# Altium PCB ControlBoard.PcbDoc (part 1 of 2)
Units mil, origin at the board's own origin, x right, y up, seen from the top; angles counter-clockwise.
Board outline 2798 x 1675 mil, 4 copper layers (Top Layer, Layer 1, Layer 2, Bottom Layer), stack 62.493 mil thick; 143 components, 84 nets, 457 pads, 255 vias.
Unrouted connection lines stored in the file: 49.
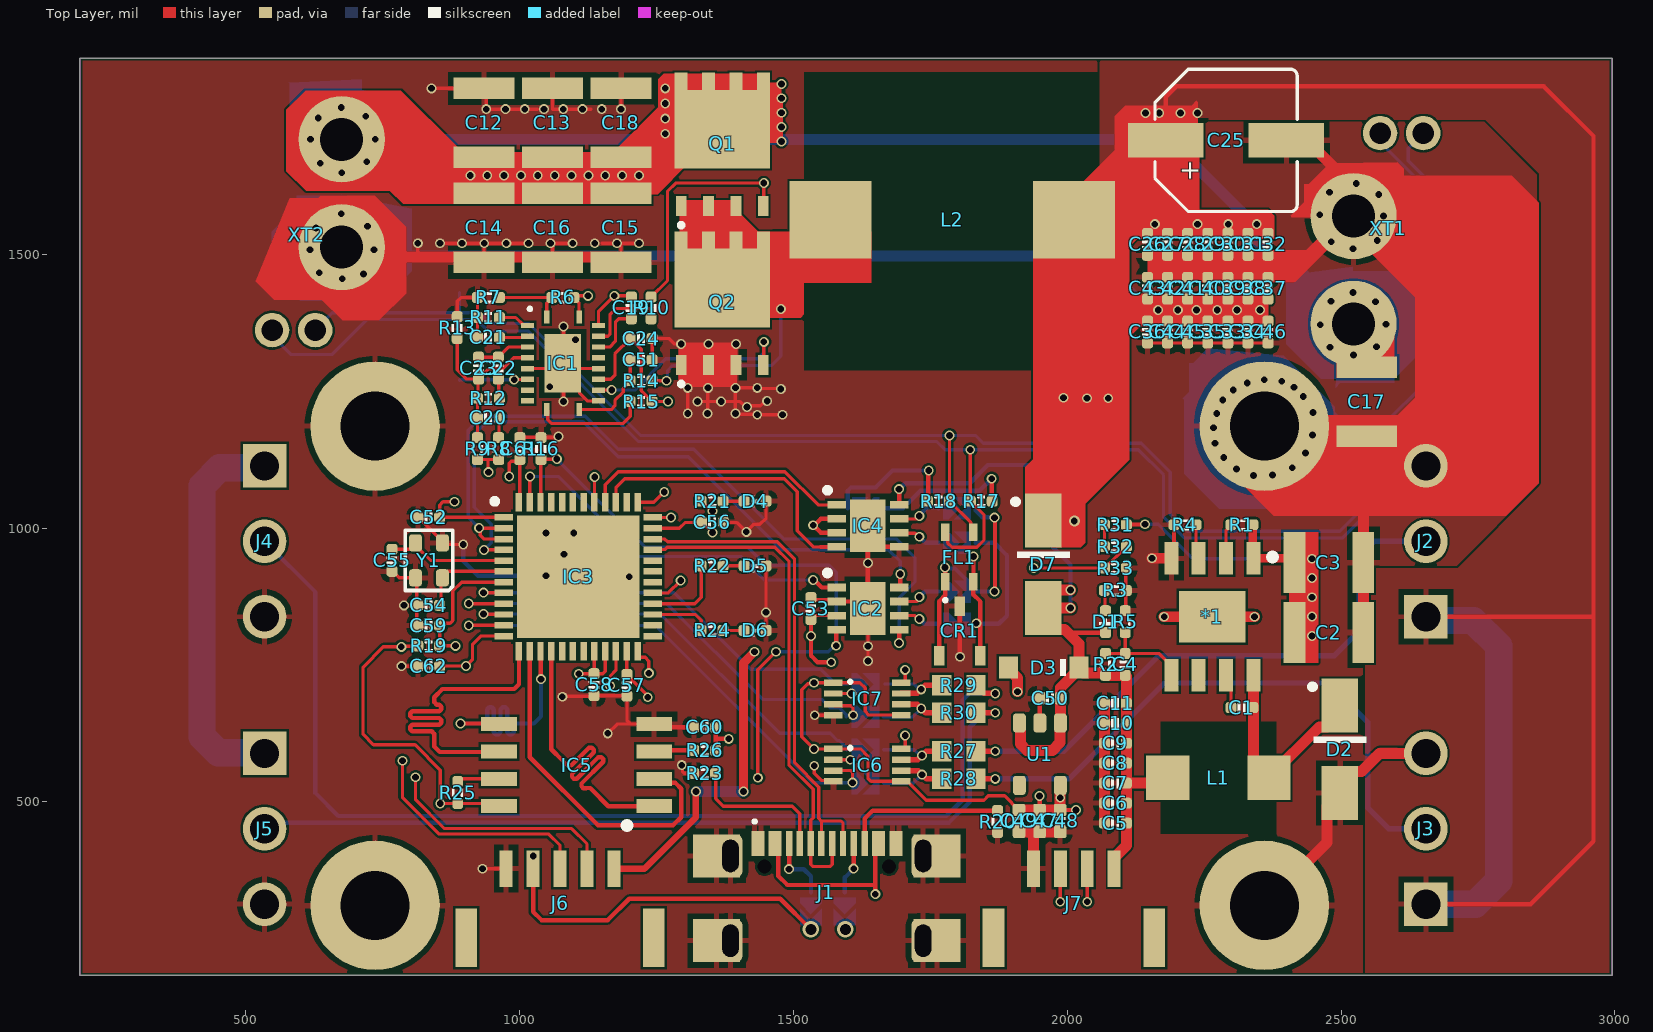
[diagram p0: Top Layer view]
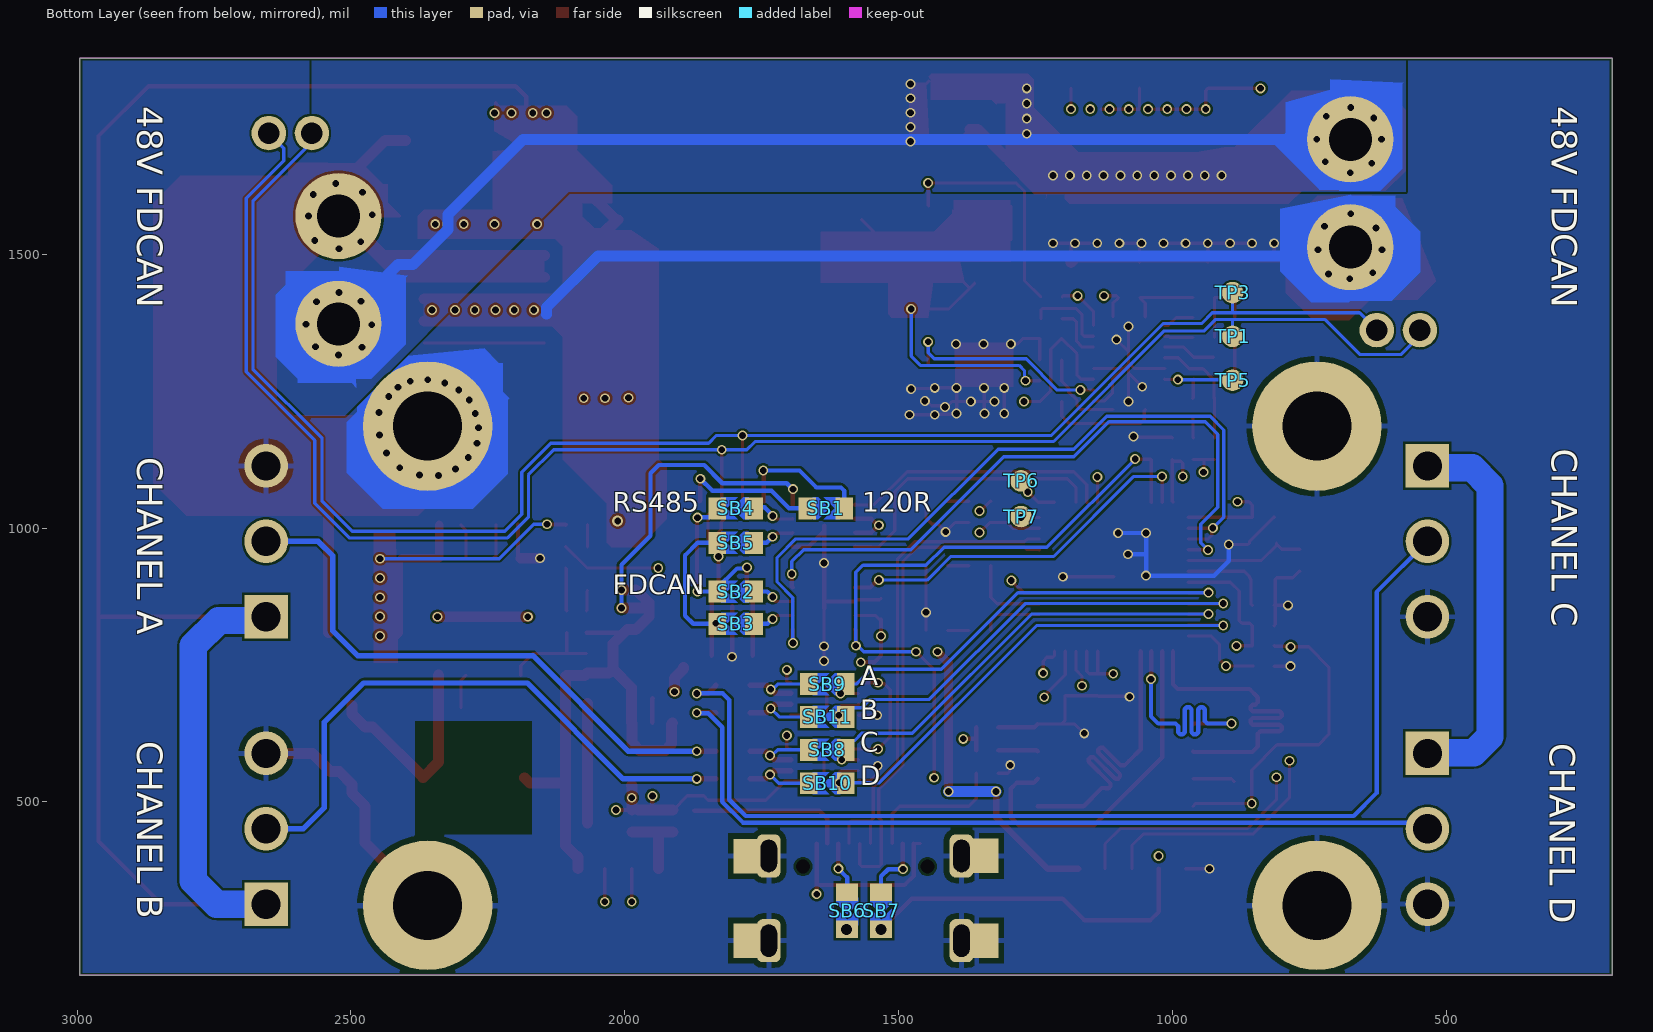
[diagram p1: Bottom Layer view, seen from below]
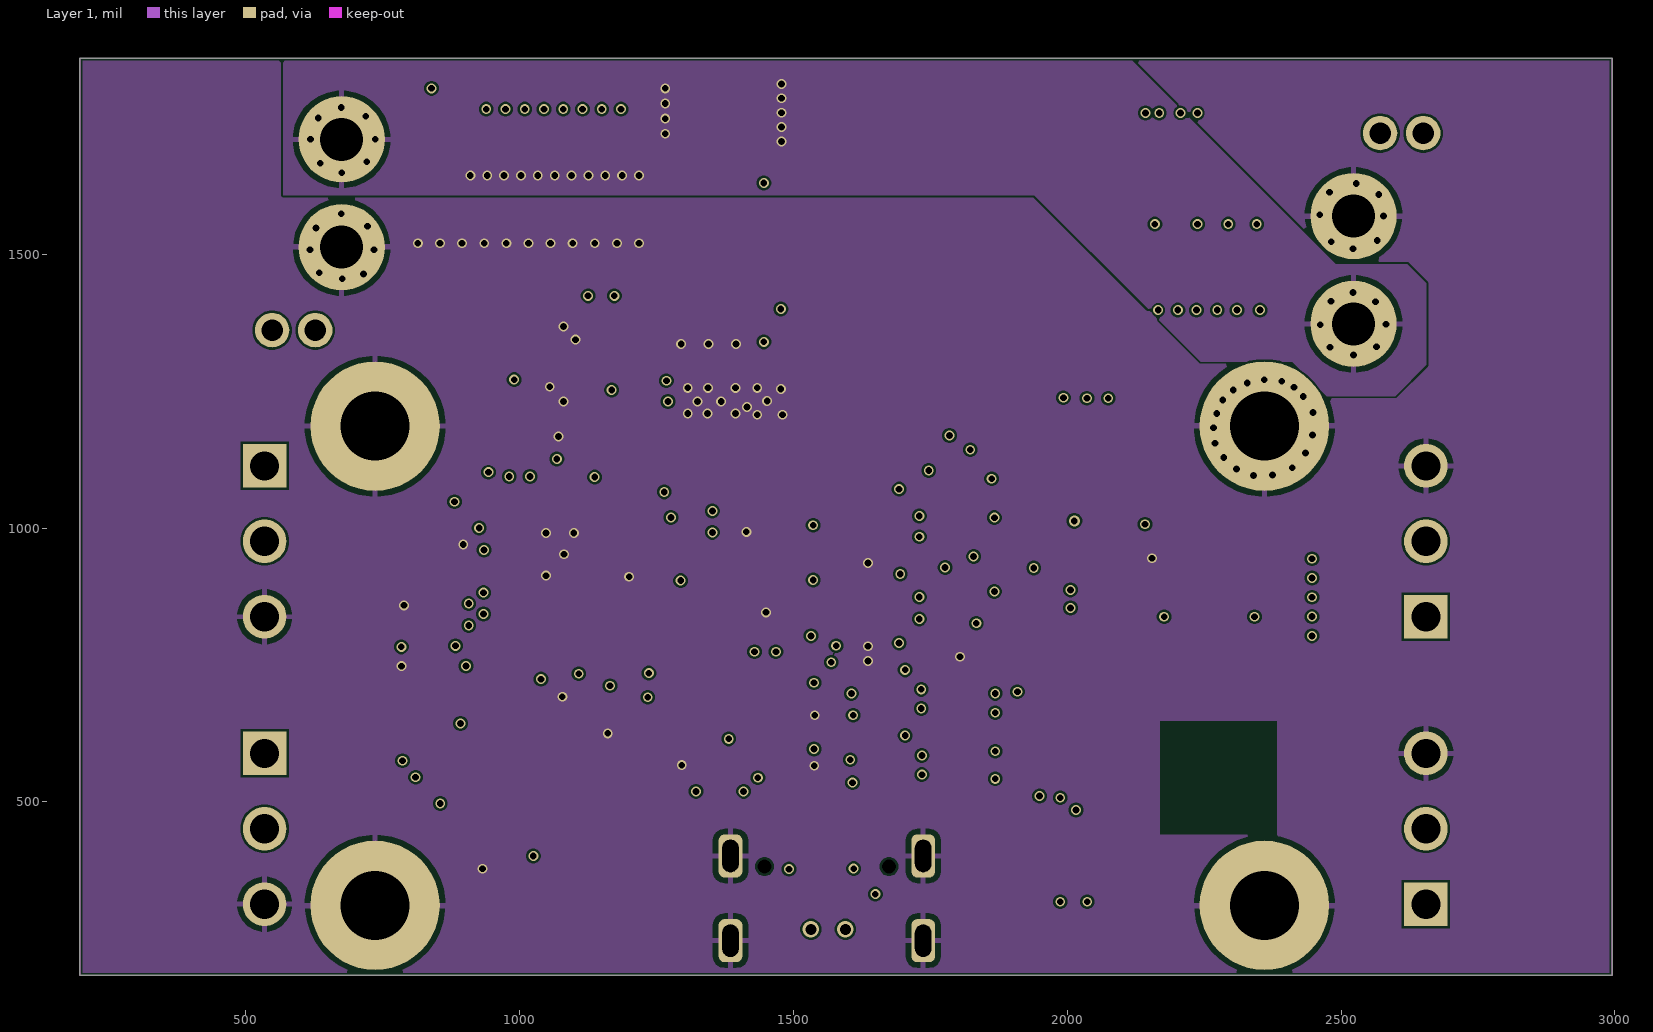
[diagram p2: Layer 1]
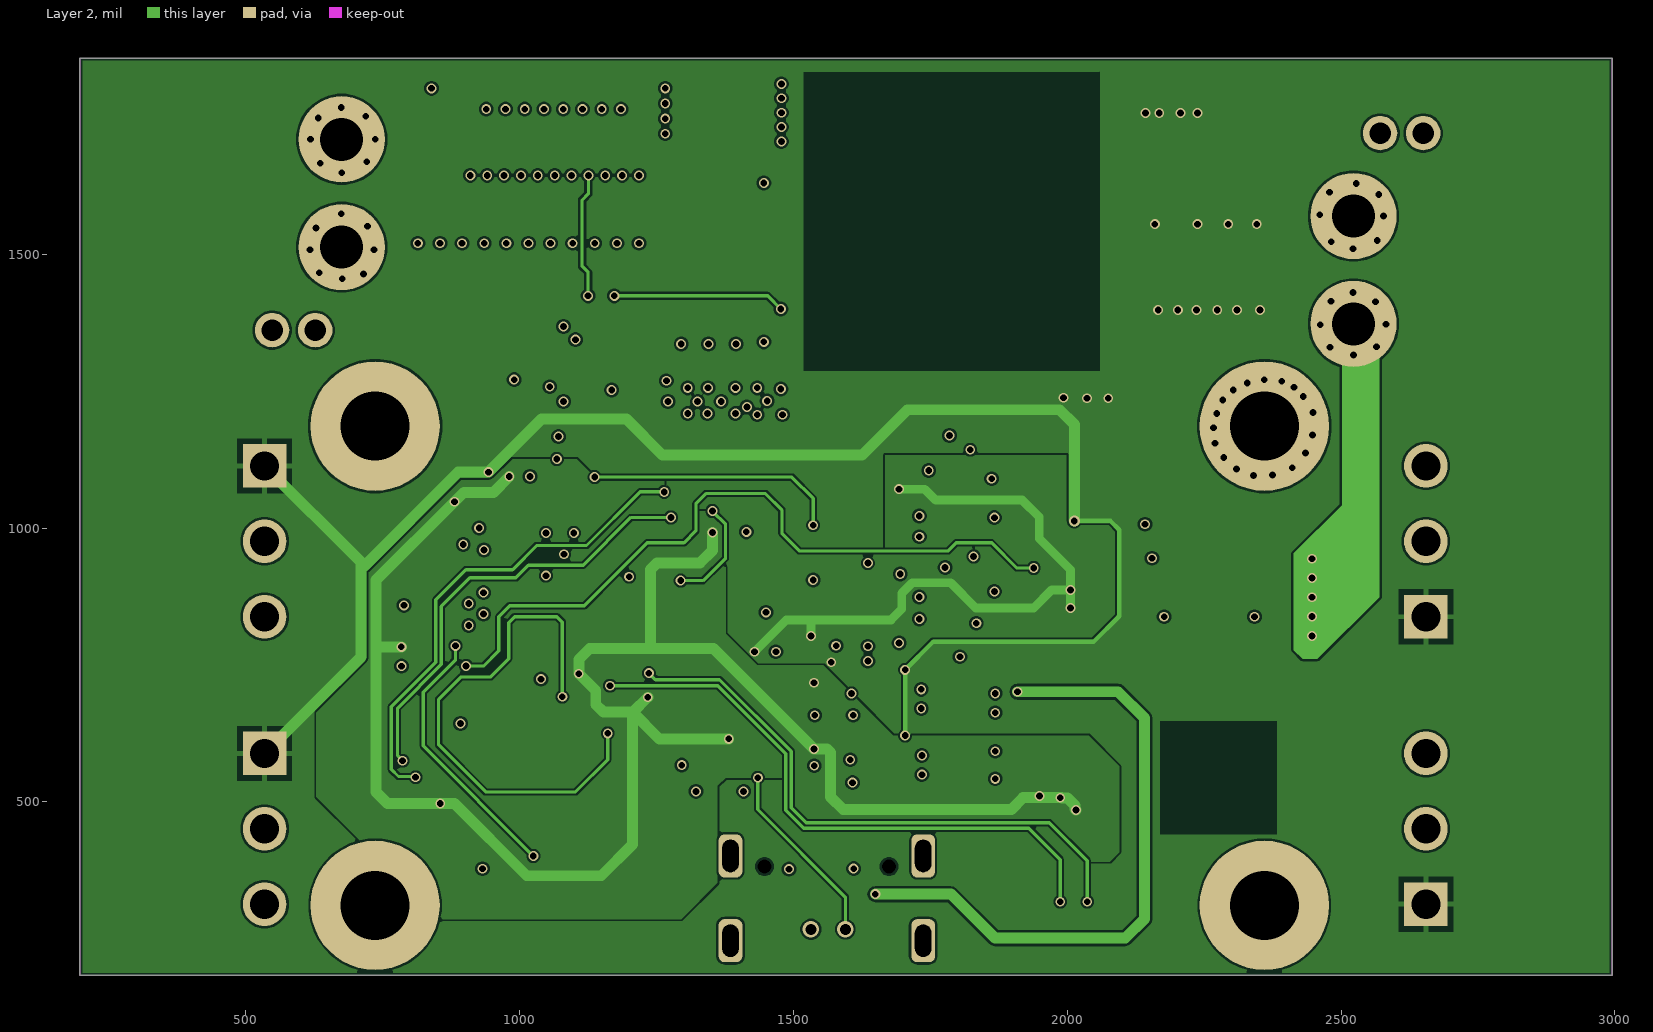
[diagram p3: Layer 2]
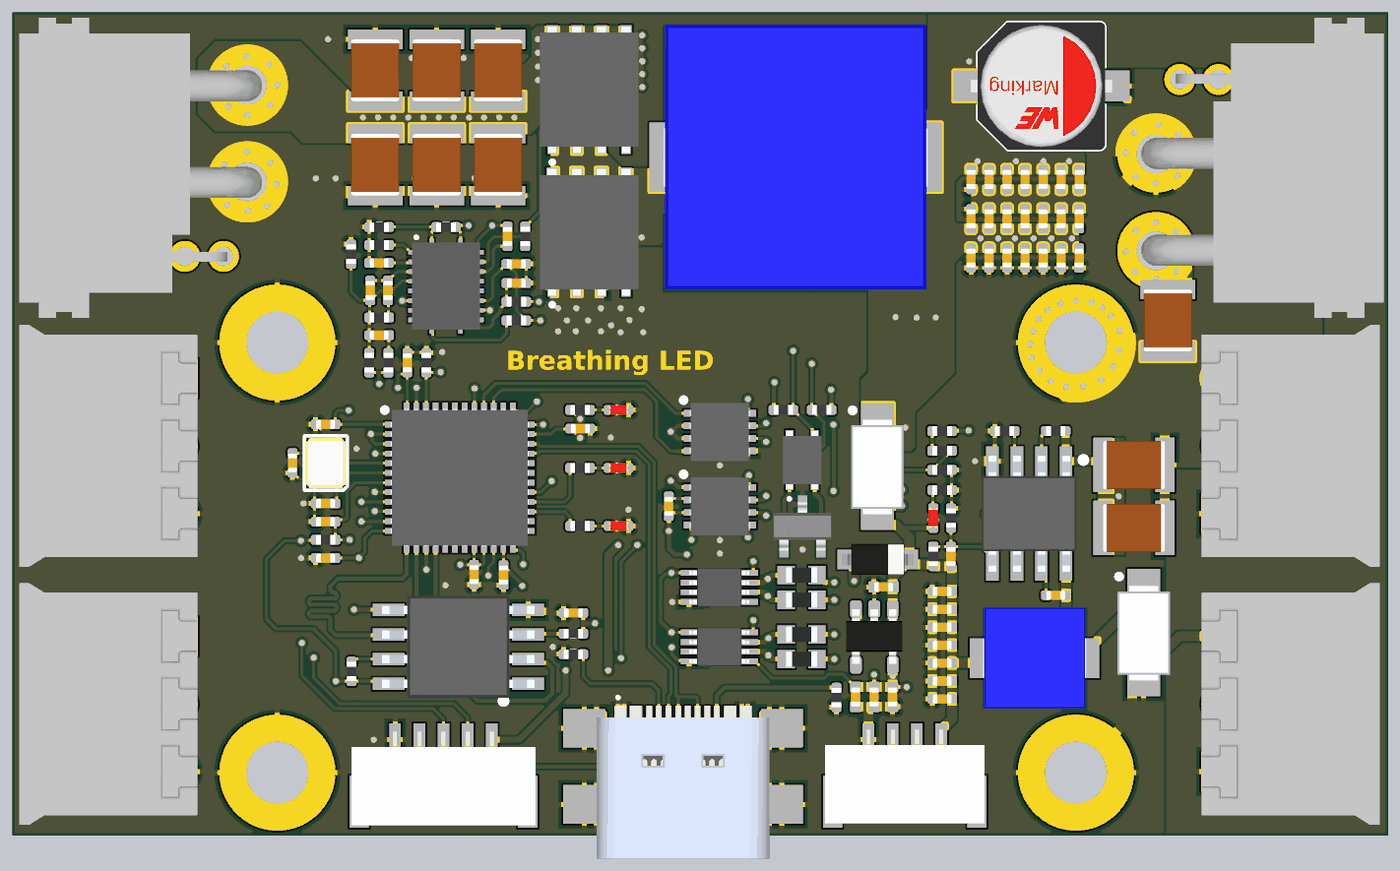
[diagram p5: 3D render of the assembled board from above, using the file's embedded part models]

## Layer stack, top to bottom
Top Solder: solder mask 0.4, Solder Resist, Dk 3.5
Top Layer: signal copper 1.4
Dielectric 2: prepreg 8.2835, PP-006, Dk 4.1
Layer 1: signal copper 0.5984
Dielectric 1: dielectric 41.9291, FR-4, Dk 4.8
Layer 2: signal copper 0.5984
Dielectric 3: prepreg 8.2835, PP-006, Dk 4.1
Bottom Layer: signal copper 1.4
Bottom Solder: solder mask 0.4, Solder Resist, Dk 3.5

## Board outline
197,183 197,1858 2995,1858 2995,183

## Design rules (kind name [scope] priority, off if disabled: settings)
Clearance [All] p1: gap=4.1 ignorepadtopadclearanceinfootprint=FALSE
PlaneConnect [All] p1: pad.planeconnectstyle=Relief pad.reliefexpansion=20 pad.reliefentries=4 pad.reliefconductorwidth=10 pad.reliefairgap=10 via.planeconnectstyle=Direct via.reliefexpansion=20 via.reliefentries=4 via.reliefconductorwidth=10 via.reliefairgap=10
PolygonConnect [All] p1: thpad.connectstyle=Relief thpad.reliefconductorwidth=10 thpad.reliefentries=4 thpad.polygonreliefangle="90 Angle" thpad.airgapwidth=10 smdpad.connectstyle=Relief smdpad.reliefconductorwidth=10 smdpad.reliefentries=4 smdpad.polygonreliefangle="90 Angle" smdpad.airgapwidth=10 via.connectstyle=Direct via.reliefconductorwidth=10 via.reliefentries=4 via.polygonreliefangle="90 Angle" via.airgapwidth=10
RoutingVias [All] p1: holewidth=12.3 width=18 viastyle="Through Hole" minholewidth=12.3 minwidth=18 maxholewidth=20 maxwidth=30
SolderMaskExpansion [All] p1: expansion=4 istentingtop=FALSE
Width [All] p1: maxlimit=200 minlimit=6 preferedwidth=8
29 further rules are at their usual default settings.

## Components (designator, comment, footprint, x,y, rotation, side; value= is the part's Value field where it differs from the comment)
*1 "SY8513FCC" SOIC127P600X170-9N 2265,838 r270 top
C1 "100nF" CAP_0402 2319,672 r180 top value=0.1u
C2 "4.7uF 100V" CAPC3225X200N 2478,809 r180 top
C3 "0.1uF 100V" CAPC3225X200N 2478,937 r180 top
C4 "220pF" CAP_0402 2106,751 r270 top value=0.1u
C5 "10uF" CAP_0402 2088,461 r0 top value=0.1u
C6 "10uF" CAP_0402 2088,497.5 r0 top value=0.1u
C7 "10uF" CAP_0402 2088,534 r0 top value=0.1u
C8 "10uF" CAP_0402 2088,570.5 r0 top value=0.1u
C9 "10uF" CAP_0402 2088,607 r0 top value=0.1u
C10 "10uF" CAP_0402 2088,643.5 r0 top value=0.1u
C11 "10uF" CAP_0402 2088,680 r0 top value=0.1u
C12 "4.7uF 100V" CAPC3225X200N 935,1739.99 r270 top
C13 "4.7uF 100V" CAPC3225X200N 1060,1739.99 r270 top
C14 "4.7uF 100V" CAPC3225X200N 935,1548 r90 top
C15 "4.7uF 100V" CAPC3225X200N 1185,1548 r90 top
C16 "0.1uF 100V" CAPC3225X200N 1060,1548 r90 top
C17 "0.1uF 100V" CAPC3225X200N 2547,1231 r90 top
C18 "0.1uF 100V" CAPC3225X200N 1185,1739.99 r270 top
C19 "100nF" CAP_0402 1204,1402 r90 top value=0.1u
C20 "820pF" CAP_0402 943,1201 r0 top value=0.1u
C21 "47nF" CAP_0402 943,1348 r0 top value=0.1u
C22 "6.8nF" CAP_0402 961,1292 r90 top value=0.1u
C23 "150pF" CAP_0402 925,1292 r90 top value=0.1u
C24 "2.2uF" CAP_0402 1222,1346 r0 top value=0.1u
C25 "100uF 16V" WCAP-AS5H_6.3x7.7 2290,1708 r180 top value=100uF
C26 "10uF" CAP_0402 2146.67,1518 r90 top value=0.1u
C27 "10uF" CAP_0402 2183.33,1518 r90 top value=0.1u
C28 "10uF" CAP_0402 2220,1518 r90 top value=0.1u
C29 "10uF" CAP_0402 2256.67,1518 r90 top value=0.1u
C30 "10uF" CAP_0402 2293.33,1518 r90 top value=0.1u
C31 "10uF" CAP_0402 2330,1518 r90 top value=0.1u
C32 "10uF" CAP_0402 2366.67,1518 r90 top value=0.1u
C33 "10uF" CAP_0402 2293.33,1358 r90 top value=0.1u
C34 "10uF" CAP_0402 2330,1358 r90 top value=0.1u
C35 "10uF" CAP_0402 2256.67,1358 r90 top value=0.1u
C36 "10uF" CAP_0402 2146.67,1358 r90 top value=0.1u
C37 "10uF" CAP_0402 2366.67,1438 r270 top value=0.1u
C38 "10uF" CAP_0402 2330,1438 r270 top value=0.1u
C39 "10uF" CAP_0402 2293.33,1438 r270 top value=0.1u
C40 "10uF" CAP_0402 2256.67,1438 r270 top value=0.1u
C41 "10uF" CAP_0402 2220,1438 r270 top value=0.1u
C42 "10uF" CAP_0402 2183.33,1438 r270 top value=0.1u
C43 "10uF" CAP_0402 2146.67,1438 r270 top value=0.1u
C44 "10uF" CAP_0402 2183.33,1358 r90 top value=0.1u
C45 "10uF" CAP_0402 2220,1358 r90 top value=0.1u
C46 "10uF" CAP_0402 2366.67,1358 r90 top value=0.1u
C47 "10uF" CAP_0402_L 1949.5,465 r270 top value=0.1u
C48 "10uF" CAP_0402_L 1987,465 r270 top value=0.1u
C49 "10uF" CAP_0402_L 1912,465 r270 top value=0.1u
C50 "10uF" CAP_0402_L 1969,689 r180 top value=0.1u
C51 "10pF" CAP_0402 1222,1307 r0 top value=0.1u
C52 "104" CAP_0402 834,1019.78 r180 top value=103
C53 "104" CAP_0402 1532,853 r90 top value=103
C54 "18pF" CAP_0402 834,858.78 r0 top value=0.1u
C55 "18pF" CAP_0402 767,941 r90 top value=0.1u
C56 "10uF" CAP_0402 1352,1011 r180 top value=0.1u
C57 "10uF" CAP_0402 1196,713 r90 top value=0.1u
C58 "10uF" CAP_0402 1136,714 r90 top value=0.1u
C59 "1uF" CAP_0402 834,821.78 r180 top value=0.1u
C60 "10uF" CAP_0402 1338,636 r180 top value=0.1u
C61 "10uF" CAP_0402 1000.33,1145 r270 top value=0.1u
C62 "100nF" CAP_0402 834,747.78 r180 top value=0.1u
CR1 "PESD1CAN,215" SOT23_PESD1_NEX 1804,812 r90 top
D1 "color?" LED_0402_GREEN 2070,829 r90 top
D2 "SS34" DIODE_DO214AC_SMA 2498,596 r90 top
D3 "DSK36" SOD123 1957,745 r270 top
D4 "color?" LED_0402_BLUE 1430,1049 r0 top
D5 "color?" LED_0402_RED 1430,931 r0 top
D6 "color?" LED_0402_GREEN 1430,813 r0 top
D7 "SS34" DIODE_DO214AC_SMA 1956,934.02 r90 top
FL1 "ACM2520-301" ACM25203012P 1803,947 r90 top
IC1 "LM5146RGYR" LM5146RGYR 1079,1301 r0 top
IC2 "TJA1042TK/3" SON65P300X300X100-9N 1636,853 r0 top
IC3 "STM32G431CBU6" QFN50P700X700X65-49N-D 1107,911 r0 top
IC4 "SIT3088E" SON65P300X300X100-9N 1636,1004 r0 top
IC5 "W25Q32JVSSIQ" SOIC127P790X216-8N 1104,567 r180 top
IC6 "SN74LVC2T45DCUR" SOP50P310X90-8N 1635,567 r0 top
IC7 "SN74LVC2T45DCUR" SOP50P310X90-8N 1635,688 r0 top
J1 "USB-TYPE-C-018" USB4110GFA 1561,279 r0 top
J2 "284512-3" SHDRRA3W80P0X350_1X3_1250X920X745P 2655,838 r270 top
J3 "284512-3" SHDRRA3W80P0X350_1X3_1250X920X745P 2655,313 r270 top
J4 "284512-3" SHDRRA3W80P0X350_1X3_1250X920X745P 534.25,1113.59 r90 top
J5 "284512-3" SHDRRA3W80P0X350_1X3_1250X920X745P 534.25,588.59 r90 top
J6 "SM05B-GHS-TB_LF__SN_" SM05B-GHS-TB 1073.79,370 r0 top
J7 "SM04B-GHS-TB_LF__SN_" SM04B-GHS-TB 2012,370 r0 top
L1 "15uH 3A" INDPM5452X300N 2276,544 r180 top
L2 "SRP1270-3R3M" INDPM137137X700N 1790,1563 r0 top
Q1 "100V 80A" BSC070N10NS5ATMA1 1370,1700.72 r0 top
Q2 "100V 80A" BSC070N10NS5ATMA1 1370,1410.72 r0 top
R1 "100k" RES_0402 2319,1006 r180 top
R2 "105k" RES_0402 2070,751 r90 top
R3 "1k" RES_0402 2088,886 r180 top
R4 "200k" RES_0402 2215,1006 r180 top
R5 "20k" RES_0402 2106,829 r90 top
R6 "100k" RES_0402 1079,1421 r0 top
R7 "17.8k" RES_0402 943,1421 r180 top
R8 "150R" RES_0402 961.67,1145 r90 top
R9 "23.2k" RES_0402 923,1145 r90 top
R10 "2R2" RES_0402 1240,1402 r270 top
R11 "40.2k" RES_0402 943,1384.5 r180 top
R12 "7.5k" RES_0402 943,1237 r180 top
R13 "4.42k" RES_0402 886,1366 r90 top
R14 "499R" RES_0402 1222,1269 r0 top
R15 "20k" RES_0402 1222,1231 r180 top
R16 "10K" RES_0402 1039,1145 r270 top
R17 "60.4R" RES_0402 1843,1049 r0 top value=22R
R18 "60.4R" RES_0402 1765,1049 r0 top value=22R
R19 "10k" RES_0402 834,784.78 r0 top
R20 "5.1k" RES_0402 1873,464 r90 top value=22R
R21 "510R" RES_0402 1351.5,1049 r0 top
R22 "510R" RES_0402 1351.5,931 r0 top
R23 "5.1k" RES_0402 1338,552 r0 top value=22R
R24 "510R" RES_0402 1351.5,813 r0 top
R25 "10k" RES_0402 887,517 r270 top
R26 "10k" RES_0402 1338,594 r0 top
R27 "100R" RESC1608X55N 1802,592.33 r0 top
R28 "100R" RESC1608X55N 1802,542 r0 top
R29 "100R" RESC1608X55N 1802,713 r0 top
R30 "100R" RESC1608X55N 1802,662.67 r0 top
R31 "210k" RES_0402 2088,1006 r180 top
R32 "120k" RES_0402 2088,966 r0 top
R33 "20k" RES_0402 2088,927 r0 top
SB1 "Circuit Breaker" SPST-2 1488.61,1093.06 r0 bottom
SB2 "Circuit Breaker" SPST-2 1942.39,826.94 r180 bottom
SB3 "Circuit Breaker" SPST-2 1942.39,767.94 r180 bottom
SB4 "Circuit Breaker" SPST-2 1942.39,978.94 r180 bottom
SB5 "Circuit Breaker" SPST-2 1942.39,915.94 r180 bottom
SB6 "Circuit Breaker" SPST-2 1536.94,156.61 r90 bottom
SB7 "Circuit Breaker" SPST-2 1474.94,156.61 r90 bottom
SB8 "Circuit Breaker" SPST-2 1774.89,537.94 r180 bottom
SB9 "Circuit Breaker" SPST-2 1774.89,657.94 r180 bottom
SB10 "Circuit Breaker" SPST-2 1774.89,476.94 r180 bottom
SB11 "Circuit Breaker" SPST-2 1774.89,597.94 r180 bottom
TP1 "TP 1mm" "SMT Test Point" 890,1350 r270 bottom
TP3 "TP 1mm" "SMT Test Point" 890,1430 r270 bottom
TP5 "TP 1mm" "SMT Test Point" 890,1270 r90 bottom
TP6 "TP 1mm" "SMT Test Point" 1276.26,1086 r90 bottom
TP7 "TP 1mm" "SMT Test Point" 1276.26,1020.96 r90 bottom
U1 "XC6209F332" SOT23-5 1950,585 r270 top
XT1 "XT30PW(2+2)" XT30PW(2+2) 2522.83,1372.84 r270 top
XT2 "XT30PW(2+2)" XT30PW(2+2) 675,1709.85 r90 top
Y1 "16MHz/20PPM" XT-2520 834.39,940.89 r90 top

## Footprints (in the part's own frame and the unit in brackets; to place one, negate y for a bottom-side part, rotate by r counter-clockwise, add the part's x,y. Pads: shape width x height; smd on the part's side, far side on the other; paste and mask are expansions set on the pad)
ACM25203012P [mm]
  rect 0.8x0.4 smd: 1(-1.15,0.65) 2(-1.15,-0.65) 3(1.15,-0.65) 4(1.15,0.65)
  silkscreen extent -2.05,0.6 -1.95,0.7, body extent -1.51,-1 1.51,1, height 1.4
BSC070N10NS5ATMA1 [mm]
  rect 0.5x0.925 smd: 1(-1.905,-2.863) 2(-0.635,-2.863) 3(0.635,-2.863) 4(1.905,-2.863)
  rect 0.6x0.8 smd: 5(1.905,2.925) 6(0.635,2.925) 7(-0.635,2.925) 8(-1.905,2.925)
  rect 4.41x3.655 smd: 9(0,0.698)
  silkscreen extent -1.95,-3.8 -1.85,-3.7, body extent -2.54,-3.28 2.54,3.26, height 1.3
CAP_0402 [mil]
  rrect50% 20x20 smd: 1(-20,0) 2(20,0)
  silkscreen extent -7,-9 7,9, body extent -20,-10 20,10, height 20
CAP_0402_L [mil]
  rrect30% 22x23 smd: 1(-20,0) 2(20,0)
  silkscreen extent -7,-9 7,9, body extent -20,-10 20,10, height 20
CAPC3225X200N [mm]
  rect 1x2.82 smd: 1(-1.6,0) 2(1.6,0)
  body extent -1.6,-1.25 1.6,1.25, height 2.5
DIODE_DO214AC_SMA [mm] "Diode 2214AC- SMA type"
  rect 2.5x1.7 smd: 1(-2.032,0) 2(2.032,0)
  silkscreen extent 0.28,-1.24 2.9,1.28, body extent -2.53,-1.35 2.47,1.35, height 2.25
INDPM5452X300N [mm]
  rect 2x2.05 smd: 1(-2.35,0) 2(2.35,0)
  body extent -2.7,-2.6 2.7,2.6, height 3
INDPM137137X700N [mm]
  rect 3.8x3.6 smd: 1(-5.65,0) 2(5.65,0)
  body extent -6.85,-6.85 6.85,6.85, height 7
LED_0402_BLUE [mil]
  rrect50% 20x20 smd: 1(-20,0) 2(20,0)
  silkscreen extent -6,-10 6,10, body extent -20,-10 20,10, height 18
LED_0402_GREEN [mil]
  rrect50% 20x20 smd: 1(-20,0) 2(20,0)
  silkscreen extent -6,-10 6,10, body extent -20,-10 20,10, height 18
LED_0402_RED [mil]
  rrect50% 20x20 smd: 1(-20,0) 2(20,0)
  silkscreen extent -6,-10 6,10, body extent -20,-10 20,10, height 18
LM5146RGYR [mm]
  rect 0.25x0.6 smd: 1(-0.75,2.15) 10(-0.75,-2.15) 11(0.75,-2.15) 20(0.75,2.15)
  rect 0.6x0.25 smd: 2(-1.65,1.75) 3(-1.65,1.25) 4(-1.65,0.75) 5(-1.65,0.25) 6(-1.65,-0.25) 7(-1.65,-0.75) 8(-1.65,-1.25) 9(-1.65,-1.75) 12(1.65,-1.75) 13(1.65,-1.25) 14(1.65,-0.75) 15(1.65,-0.25) 16(1.65,0.25) 17(1.65,0.75) 18(1.65,1.25) 19(1.65,1.75)
  rect 1.7x2.7 smd: 21(0,0)
  silkscreen extent -1.58,2.47 -1.48,2.57, body extent -1.75,-2.25 1.75,2.25, height 1
QFN50P700X700X65-49N-D [mm]
  rect 0.85x0.3 smd: 1(-3.45,2.75) 2(-3.45,2.25) 3(-3.45,1.75) 4(-3.45,1.25) 5(-3.45,0.75) 6(-3.45,0.25) 7(-3.45,-0.25) 8(-3.45,-0.75) 9(-3.45,-1.25) 10(-3.45,-1.75) 11(-3.45,-2.25) 12(-3.45,-2.75) 25(3.45,-2.75) 26(3.45,-2.25) 27(3.45,-1.75) 28(3.45,-1.25) 29(3.45,-0.75) 30(3.45,-0.25) 31(3.45,0.25) 32(3.45,0.75) 33(3.45,1.25) 34(3.45,1.75) 35(3.45,2.25) 36(3.45,2.75)
  rect 0.3x0.85 smd: 13(-2.75,-3.45) 14(-2.25,-3.45) 15(-1.75,-3.45) 16(-1.25,-3.45) 17(-0.75,-3.45) 18(-0.25,-3.45) 19(0.25,-3.45) 20(0.75,-3.45) 21(1.25,-3.45) 22(1.75,-3.45) 23(2.25,-3.45) 24(2.75,-3.45) 37(2.75,3.45) 38(2.25,3.45) 39(1.75,3.45) 40(1.25,3.45) 41(0.75,3.45) 42(0.25,3.45) 43(-0.25,3.45) 44(-0.75,3.45) 45(-1.25,3.45) 46(-1.75,3.45) 47(-2.25,3.45) 48(-2.75,3.45)
  rect 5.7x5.7 smd: 49(0,0)
  silkscreen extent -4,3.38 -3.75,3.62, body extent -3.55,-3.55 3.55,3.55, height 0.65
RES_0402 [mil]
  rrect50% 20x20 smd: 1(-20,0) 2(20,0)
  silkscreen extent -7,-10 7,10, body extent -20,-10 20,10, height 14
RESC1608X55N [mm]
  rect 0.9x0.95 smd: 1(-0.8,0) 2(0.8,0)
  body extent -0.8,-0.4 0.8,0.4, height 0.55
SHDRRA3W80P0X350_1X3_1250X920X745P [mm]
  rect 2.025x2.025 hole 1.35: 1(0,0)
  round 2.025 hole 1.35: 2(-3.5,0) 3(-7,0)
  body extent -9.75,-1 2.75,8.2, height 7.25
SM04B-GHS-TB [mm]
  rect 0.6x1.7 smd: 1(-1.875,0.2) 2(-0.625,0.2) 3(0.625,0.2) 4(1.875,0.2)
  rect 1x2.7 smd: 5(-3.725,-3) 6(3.725,-3)
  body extent -4.12,-4.13 4.13,0.72, height 4.45
SM05B-GHS-TB [mm]
  rect 0.6x1.7 smd: 1(-2.5,0.2) 2(-1.25,0.2) 3(0,0.2) 4(1.25,0.2) 5(2.5,0.2)
  rect 1x2.7 smd: 6(-4.35,-3) 7(4.35,-3)
  body extent -4.75,-4.23 4.75,0.63, height 4.45
"SMT Test Point" [mm]
  round 1 smd paste-0.5: 1(0,0)
  body extent -0.5,-0.5 0.5,0.5, height 0.1
SOD123 [mm]
  rect 1.02x0.88 smd: 1(0,-1.635) 2(0,1.635)
  silkscreen extent -0.38,0.76 0.38,1.02, body extent -0.8,-1.85 0.81,1.85, height 1.27
SOIC127P600X170-9N [mm]
  rect 1.525x0.65 smd: 1(-2.712,1.905) 2(-2.712,0.635) 3(-2.712,-0.635) 4(-2.712,-1.905) 5(2.712,-1.905) 6(2.712,-0.635) 7(2.712,0.635) 8(2.712,1.905)
  rect 2.4x3.1 smd: 9(0,0)
  silkscreen extent -2.78,2.8 -2.77,2.8, body extent -3,-2.45 3,2.45, height 1.7
SOIC127P790X216-8N [mm]
  rect 1.65x0.65 smd: 1(-3.6,1.905) 2(-3.6,0.635) 3(-3.6,-0.635) 4(-3.6,-1.905) 5(3.6,-1.905) 6(3.6,-0.635) 7(3.6,0.635) 8(3.6,1.905)
  silkscreen extent -2.34,2.8 -2.33,2.8, body extent -3.95,-2.64 3.95,2.64, height 2.16
SON65P300X300X100-9N [mm]
  rect 0.85x0.35 smd: 1(-1.45,0.975) 2(-1.45,0.325) 3(-1.45,-0.325) 4(-1.45,-0.975) 5(1.45,-0.975) 6(1.45,-0.325) 7(1.45,0.325) 8(1.45,0.975)
  rect 1.65x2.45 smd: 9(0,0)
  silkscreen extent -2,1.53 -1.75,1.77, body extent -1.55,-1.5 1.55,1.5, height 1
SOP50P310X90-8N [mm]
  rect 0.85x0.3 smd: 1(-1.575,0.75) 2(-1.575,0.25) 3(-1.575,-0.25) 4(-1.575,-0.75) 5(1.575,-0.75) 6(1.575,-0.25) 7(1.575,0.25) 8(1.575,0.75)
  silkscreen extent -0.79,0.79 -0.79,0.8, body extent -1.55,-1 1.55,1, height 0.77
SOT23-5 [mm] "SOT23, 3-Leads, Body 3.1x3.0mm (max), Pitch 0.95mm, IPC Medium Density"
  rrect50% 0.889x0.6 smd: 1(-1.5,0.95) 2(-1.5,0) 3(-1.5,-0.95) 4(1.396,-0.95) 5(1.396,0.95)
  body extent -1.48,-1.45 1.32,1.45, height 1.2
SOT23_PESD1_NEX [mil]
  rect 35.5x19 smd paste+0 mask+0: 1(-45.25,37.4) 2(-45.25,-37.4) 3(45.25,0)
  body extent -49,-59 49,59, height 43
SPST-2 [mil]
  rect 32x40 smd: 1(178.39,57.06) 2(110.89,57.06)
  Top Layer region: 168.39,77.06 158.39,77.06 138.39,57.06 158.39,37.06 168.39,37.06
  Top Layer region: 118.39,57.06 128.39,57.06 148.39,77.06 118.39,77.06
  Top Layer region: 118.39,57.06 128.39,57.06 148.39,37.06 118.39,37.06
USB4110GFA [mm]
  rect 2x1.6 smd far side: 1(-5.176,-0.827) 2(-5.176,3.103) 19(5.105,3.094) 20(5.105,-0.827)
  rect 2.18x2 smd: 1(-5.11,-0.827) 2(-5.11,3.103) 19(5.11,3.103) 20(5.11,-0.827)
  rrect50% 1.1x2 hole 1.5 slot 0.762 at 0 deg: 1(-4.47,-0.827) 2(-4.47,3.103) 19(4.47,3.103) 20(4.47,-0.827)
  rect 0.3x1.15 smd: 3(-3.35,3.678) 4(-3.05,3.678) 5(-2.55,3.678) 6(-2.25,3.678) 7(-1.75,3.678) 8(-1.25,3.678) 9(-0.75,3.678) 10(-0.25,3.678) 11(0.25,3.678) 12(0.75,3.678) 13(1.25,3.678) 14(1.75,3.678) 15(2.25,3.678) 16(2.55,3.678) 17(3.05,3.678) 18(3.35,3.678)
  round 0.325 hole 0.65 unplated: MH1(-2.89,2.603) MH2(2.89,2.603)
  silkscreen extent -3.4,4.65 -3.3,4.75, body extent -4.47,-3.63 4.47,4.27, height 3.2
WCAP-AS5H_6.3x7.7 [mm] "Polarized capacitors, Aluminum Electrolytic Capacitors, 2-Leads, Body 6.3x7.7x2.2"
  rect 3.5x1.6 smd: 1(2.8,0) 2(-2.8,0)
  silkscreen extent -3.3,-3.3 3.3,3.3, body extent -3.65,-3.3 3.65,3.3, height 7.7
XT30PW(2+2) [mm]
  round 4 hole 2: 1(0,0) 2(-5,0)
  round 1.6 hole 1: 3(-8.85,1.23) 4(-8.85,3.23)
  body extent -12.03,-0.76 3.47,11.77, height 5
XT-2520 [mm]
  rrect50% 0.8x0.6 smd: 1(-0.81,-0.625) 2(0.81,-0.625) 3(0.81,0.625) 4(-0.81,0.625)
  silkscreen extent -1.4,-1.1 1.4,1.1, body extent -1.3,-1.05 1.3,1.05, height 0.55

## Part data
C1 C4 C5 C6 C7 C8 C9 C10 C11 C19 C20 C21 C22 C23 C24 C26 C27 C28 C29 C30 C31 C32 C33 C34 C35 C36 C37 C38 C39 C40 C41 C42 C43 C44 C45 C46 C47 C48 C49 C50 C51 C54 C55 C56 C57 C58 C59 C60 C61 C62: library part C_0402, "Capacitor"
C2 C3 C12 C13 C14 C15 C16 C17 C18: library part C_1210, "X7R 100V 1uF ±10% 1210 Multilayer Ceramic Capacitors MLCC - SMD/SMT ROHS", Arrow Part Number=C3225X7S3D102M200AA, Manufacturer_Name=TDK, Mouser Part Number=810-C3225X7S3D102M2A
C25: library part CAP/100uF/16V/865230345005, "WCAP-AS5H Aluminum Electrolytic Capacitors, 100uF", PartNumber=865230345005, RatedVoltage=16V
C52 C53: library part CM, "Cap SMD"
CR1: "No Description Available", Mfr_Name=Nexperia
D1: library part LED_0402, "LED RES"
D2 D7: "DIODE SCHOTTKY 40V 3A SMA"
D3: library part "1N4007 SOD123", "DSK36 60V 3A"
D4 D5 D6: library part LED_0402, "LED"
FL1: library part ACM2520-301-2PL-TL01_1, "Common Mode Filters", Arrow Part Number=ACM9070-701-2PL-TL01, Manufacturer_Name=TDK, Mouser Part Number=810-ACM90707012PLTL
IC1: "Integrated Circuit", Manufacturer_Name="Texas Instruments", Mouser Part Number=595-LM5146RGYR
IC2: library part SIT1044QTK/3, "https://item.taobao.com/item.htm?spm=a21n57.1.0.0.730f50e55xYJuK&id=715328337189&ns=1&abbucket=13#detail", Arrow Part Number=TJA1044VTKZ, Manufacturer_Name=NXP, Mouser Part Number=771-TJA1044VTKZ
IC3: "Integrated Circuit", Manufacturer_Name=STMicroelectronics, Mouser Part Number=511-STM32G431CBU6
IC4: "Integrated Circuit", Arrow Part Number=SN65HVD485EDGKR, Manufacturer_Name="Texas Instruments", Mouser Part Number=595-SN65HVD485EDGKR
IC5: "Integrated Circuit", Manufacturer_Name=Winbond, Mouser Part Number=454-W25Q32JVSSIQ
IC6 IC7: "Integrated Circuit", Manufacturer_Name="Texas Instruments", Mouser Part Number=595-SN74LVC2T45DCUR
J1: library part USB4110-GF-A, "USB-TYPE-C-018 C2927038 3A 1 Horizontal attachment 16P Female -25℃~+85℃ Type-C SMD USB Connectors ROHS", Manufacturer_Name="GCT (GLOBAL CONNECTOR TECHNOLOGY)"
J2 J3 J4 J5: "284512-3 3P 3.5mm", Manufacturer_Name="TE Connectivity", Mouser Part Number=571-284512-3
J6: "1.25mm Pitch 5 Way Shrouded Right Angle PCB Header", Arrow Part Number=SM05B-GHS-TB(LF)(SN), Manufacturer_Name="JST (JAPAN SOLDERLESS TERMINALS)", Mouser Part Number=N/A
J7: "1.25mm Pitch 4 Way Shrouded Right Angle PCB Header", Arrow Part Number=SM04B-GHS-TB(LF)(SN), Manufacturer_Name="JST (JAPAN SOLDERLESS TERMINALS)", Mouser Part Number=N/A
L1: library part SLO0530H3R3MTT, "SMMS0530-100M", Manufacturer_Name="Sunltech Tech"
L2: "SRP1270-3R3M 13.7*13.7mm", Manufacturer_Name=Bourns, Mouser Part Number=652-SRP1270-3R3M
Q1 Q2: library part BSC070N10NS5, "BSC070N10NS5 MOSFET (N-Channel)", Arrow Part Number=NTMFS5C628NLT3G, Manufacturer_Name=onsemi, Mouser Part Number=863-NTMFS5C628NLT3G
R1 R2 R3 R4 R5 R6 R7 R8 R9 R10 R11 R12 R13 R14 R15 R16 R19 R21 R22 R24 R25 R26 R31 R32 R33: library part R, "Resistor R1/4W"
R17 R18 R20 R23: library part R-0402, "Resistor"
R27 R28 R29 R30: library part R_0603, "Resistor R1/4W"
SB1 SB2 SB3 SB4 SB5 SB6 SB7 SB8 SB9 SB10 SB11: library part CB
TP1 TP3 TP5 TP6 TP7: "PCB TEST POINT SMT 1mm"
U1: library part XC6209F332MR-G, "IC REG LINEAR 3.3V 300MA SOT25", MFR="Torex Semiconductor Ltd"
Y1: library part XT-4Pin, "XT-2520", Package="SMD-6 ECS International"

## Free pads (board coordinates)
  round 236.22 hole 125.98: 7(736,311) 7(736,1186) 7(2360,311) 7(2360,1186)

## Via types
v1: diameter 18, hole 12.3, Top Layer to Bottom Layer, tented both sides, 252 vias
v2: diameter 30, hole 20, Top Layer to Bottom Layer, 2 vias
v3: diameter 20, hole 12.3, Top Layer to Bottom Layer, tented both sides, 1 vias

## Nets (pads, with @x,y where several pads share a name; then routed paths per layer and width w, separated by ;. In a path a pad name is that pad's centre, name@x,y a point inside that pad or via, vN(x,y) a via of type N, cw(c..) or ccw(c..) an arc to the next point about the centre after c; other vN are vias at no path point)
3V3: C47.1 C48.1 C49.1 C52.1 C56.2 C57.2 C58.2 C60.1 C61.2 IC3.1 IC3.20 IC3.21 IC3.23 IC3.35 IC3.48 IC5.8 IC6.1 IC6.5 IC7.1 IC7.5 R19.1 R25.2 R26.2 U1.5 | length 5634.1
  Top Layer w6: R19.1@814,784.78 813.11,783.89 784.89,783.89 v1(784,783) 751,783 714,746 714,623 733,604 809,604 855,558 v1(855,497) R25.2@887,497 957.27,497 IC5.8@962.27,492 ; v1(881,1048) 860,1048 854,1042 C52.1@854,1019.78 854.26,1019.52 970.92,1019.52 IC3.1@971.17,1019.27 ; v1(981,1094) 981,1118.5 984.51,1122.02 997.35,1122.02 C61.2@1000.33,1125 1000.33,1048.43 IC3.48@998.73,1046.83 ; v1(1108,734) C58.2@1136,734 ; IC3.20@1136.53,775.17 1136.26,774.91 1136.26,734.26 C58.2@1136,734 ; IC3.21@1156.21,775.17 1156.21,738.21 1152,734 C58.2@1136,734 ; IC3.23@1195.58,775.17 1195.79,774.96 1195.79,732.13 1234,693.92 v1(1234,691) ; IC3.35@1242.83,999.58 1291.58,999.58 1302,1010 1333.5,1010 1351.5,992 v1(1352,992) ; IC7.5@1697.01,658.47 1637.53,658.47 1631,665 1631,708 1621.47,717.53 IC7.1@1572.99,717.53 v1(1537.53,717.53) 1535.8,715.8 1525.8,715.8 1515,705 1515,619.06 v1(1537.53,596.53) IC6.1@1572.99,596.53 1622.47,596.53 1636,583 1636,543 1641.53,537.47 IC6.5@1697.01,537.47 1707.83,537.47 1742.31,503 1848,503 1856,511 1885.5,511 1911.5,485 C49.1@1912,485
  Top Layer w8: R26.2@1358,594 1358,615 ; C60.1@1358,636 1358,615 ; v1(1381.9,615) 1358,615 ; C47.1@1949.5,485 v1(1949.5,510.5) ; 1975,485 C48.1@1987,485 v1(2016,485)
  Top Layer w20: C49.1@1912,485 C47.1@1949.5,485 1975,485 ; C48.1@1987,485 1987.2,485.2 v1(1987.2,507.53) 1987.2,529.85 U1.5@1987.4,530.06
  Layer 2 w20: v1(784,783) 739,783 738,782 ; v1(981,1094) 952,1065 898,1065 v1(881,1048) 738,905 738,782 ; v1(1234,691) 1207,664 1206,664 ; v1(1352,992) 1352,959 1329,936 1250.72,936 1239,924.28 1239,780 ; v1(1381.9,615) 1255,615 1206,664 ; v1(2016,485) 2014.09,486.91 2014.09,493.54 2000.5,507.13 1990.31,507.13 1989.91,507.53 1949.5,507.53 1919.53,507.53 1898,486 1591,486 1568,509 1568,590 1561.47,596.53 v1(1537.53,596.53) 1354.06,780 1239,780 ; 738,782 738,518 759,497 v1(855,497) 881,497 1013,365 1149,365 1206,422 1206,664 ; 1206,664 1153,664 1139,678 1139,703 v1(1108,734) 1108,760 1128,780 1239,780
5VDC: C4.2 C5.2 C6.2 C7.2 C8.2 C9.2 C10.2 C11.2 C50.1 C53.1 D1.1 D3.2 D7.1 IC2.3 IC4.8 J6.5 J7.4 L1.2 R2.1 U1.1 U1.3 | length 3698.3
  Top Layer w6: C53.1@1532,832 1533.08,832 1541.29,840.2 IC2.3@1578.91,840.2
  Top Layer w8: C53.1@1532,833 1532,832 v1(1532,803) 1532,767 1544,755 v1(1569,755) ; v1(1693,1071) 1693,1042.47 IC4.8@1693.09,1042.39 ; D7.1@1956,857.54 1985.46,887 v1@2005,887 ; 2001,809 D1.1@2070,809
  Top Layer w12: J6.5@1172.21,377.87 1227.87,377.87 1322,472 v1@1322,516
  Top Layer w16: v1(1409,519) 1409,754 v1(1429,774)
  Top Layer w20: U1.3@1912.6,644.06 1914.41,642.24 1914.41,605.72 1926.13,594 1973,594 1987,608 1987,643.65 U1.1@1987.4,644.06 1987.4,708.28 D3.2@2021.37,742.24 ; v1(2006,854) D7.1@1956,854 ; v1(2006,887) 1985.46,887 1979.46,887 1956,863.54 1956,857.54 D7.1@1956,854 ; J7.4@2085.82,377.87 2085.82,399.53 2087.63,401.34 2089.08,401.34 2108,420.26 C6.2@2108,497.5 C7.2@2108,534 ; L1.2@2183.48,544 2173.48,534 C7.2@2108,534 ; D7.1@1956,854 1956,838.25 1979.46,814.79 1995.21,814.79 2001,809 2021.37,788.63 D3.2@2021.37,745 D3.2@2021.37,742.24 ; D3.2@2021.37,742.24 2028.69,734.92 2068.69,734.92 2072.61,731 C4.2@2106,731 2108,729 C11.2@2108,680 C10.2@2108,643.5 C9.2@2108,607 C8.2@2108,570.5 C7.2@2108,534
  Layer 2 w16: v1(1429,774) 1487,832 1532,832 ; v1(1532,803) 1532,832 ; v1(1693,1071) 1740,1071 1760,1051 1918,1051 1949,1020 1949,981 2006,924 v1(2006,887) ; v1(2006,854) v1(2006,887) ; 1532,832 1678,832 1698,852 1698,881 1717,900 1787,900 1833,854 1939,854 1972,887 v1(2006,887)
  Bottom Layer w8: v1(1693,1071) 1704,1082 1822,1082 1855,1115 1938,1115 1953,1100 1953,986 2006,933 v1(2006,887) v1(2006,854)
  Bottom Layer w20: v1(1322,519) v1(1409,519)
5VDC_LED: C25.1 C26.2 C27.2 C28.2 C29.2 C30.2 C31.2 C32.2 C33.2 C34.2 C35.2 C36.2 C37.2 C38.2 C39.2 C40.2 C41.2 C42.2 C43.2 C44.2 C45.2 C46.2 D7.2 IC6.8 IC7.8 J2.1 J3.1 J4.1 J5.1 L2.2 R8.1 R9.1 | length 9721.1
  Top Layer w6: R9.1@923,1125 942.33,1125 ; v1(943,1102) 942.33,1102.67 942.33,1125 ; R8.1@961.67,1125 942.33,1125 ; IC6.8@1697.01,596.53 1701.09,596.53 1704,599.43 v1(1704,621) ; IC7.8@1697.01,717.53 1701.09,717.53 1704,720.43 v1(1704,741)
  Top Layer w8: D7.2@1956,1014.03 1957.03,1013 v3(2013,1013) ; 1956,1066.02 D7.2@1964.02,1058 ; v1@1992,1238 v1(1993,1238) ; v1(2036,1237) v1@2036,1238 ; C25.1@2170.5,1708 2143,1735.5 v1(2143,1758) v1(2168,1758) 2179.76,1758 ; C25.1@2179.76,1708 2179.76,1758 ; v1(2238,1758) v1(2207,1758) 2179.76,1758 ; J3.1@2655,313 2846,313 2961,428 2961,838 ; J2.1@2655,838 2961,838 ; 2179.76,1758 2179.76,1787.76 2199,1807 2870,1807 2961,1716 2961,838
  Top Layer w20: 1956,1066.02 1956,1118 v1(2075,1237) 2075,1389.72 ; C25.1@2179.76,1708 2170.5,1708 2142.36,1708 2077.24,1642.88 2077.24,1623.87 2016.38,1563 L2.2@2015.42,1563 ; v1@2238,1557 v1@2238,1560 ; v1@2274,1399 v1@2275,1399 ; v1@2346,1554 v1(2346,1555) ; v1(2352,1398) v1@2357,1398 ; C46.2@2366.67,1378 C34.2@2330,1378 C33.2@2293.33,1378 C35.2@2256.67,1378 C45.2@2220,1378 C44.2@2183.33,1378 C36.2@2146.67,1378 2086.72,1378 2075,1389.72 ; C37.2@2366.67,1418 C38.2@2330,1418 C39.2@2293.33,1418 C40.2@2256.67,1418 C41.2@2220,1418 C42.2@2183.33,1418 C43.2@2146.67,1418 2088,1418 2076.28,1429.72 2076.28,1502.13 L2.2@2040.42,1538 ; C32.2@2366.67,1538 C31.2@2330,1538 C30.2@2293.33,1538 C29.2@2256.67,1538 C28.2@2220,1538 C27.2@2183.33,1538 C26.2@2146.67,1538 L2.2@2040.42,1538 ; L2.2@2014.13,1563 L2.2@2015.42,1563 ; L2.2@2014.13,1563 L2.2@2039.13,1538 ; L2.2@2014.13,1563 L2.2@2012.44,1563 2037.44,1538 L2.2@2039.13,1538 ; L2.2@2015.42,1563 L2.2@2040.42,1538 ; L2.2@2039.13,1538 L2.2@2040.42,1538 ; L2.2@2039.13,1538 2075,1502.13 2075,1429.72 2075,1389.72
  Layer 2 w8: v1(1704,621) v1(1704,741) 1755,792 2048,792 2095,839 2095,997 2079,1013 v3(2013,1013)
  Layer 2 w20: J5.1@534.25,588.59 710,764.34 710,937.84 ; J4.1@534.25,1113.59 710,937.84 ; v3(2013,1013) 2013,1189 1986,1216 1708,1216 1625,1133 1261,1133 1195,1199 1040,1199 v1(943,1102) 887.84,1102 716.84,931 710,937.84
  Bottom Layer w50: J5.1@534.25,588.59 520.22,588.59 519.39,589.42 449.29,589.42 420,618.71 420,1077.49 452.28,1109.77 530.43,1109.77 J4.1@534.25,1113.59 ; J3.1@2655,313 2745.49,313 2788,355.51 2788,785 2741.9,831.1 2661.9,831.1 J2.1@2655,838
  other v1: 2166,1398 2202,1398 2236,1398 2274,1398 2310,1398 2160,1555 2238,1555 2294,1555
CAN_VIO: IC2.5 IC3.2 IC3.3 | length 1418.2
  Top Layer w6: v1(926,1000) v1@926.21,999.79 ; IC3.3@971.17,979.9 935.1,979.9 928.3,986.7 928.3,997.7 v1@926.21,999.79 ; IC3.2@971.17,999.58 970.96,999.79 v1@926.21,999.79
  Top Layer w8: v1(1693,790) 1693,814.53 IC2.5@1693.09,814.61
  Bottom Layer w6: v1(926,1000) 906,1020 906,1179 931,1204 1120,1204 1180,1144 1318,1144 1482,980 1688,980 1722,946 1722,902 1693,873 v1(1693,790)
DEBUG_RX: IC3.24 J7.3 | length 1194.4
  Top Layer w6: IC3.24@1215.27,775.17 1215.27,766.69 1218.17,763.78 1229.22,763.78 1236,757 v1(1236,735) ; v1@2036.61,316.61 v1(2036.61,317.39) J7.3@2036.61,377.87
  Layer 2 w6: v1(1236,735) 1248,723 1365,723 1496,592 1496,489 1523,462 1967,462 2036.61,392.39 v1(2036.61,317.39)
DEBUG_TX: IC3.22 J7.2 | length 1219.6
  Top Layer w6: v1(1165,712) 1165,729 1175.9,739.9 IC3.22@1175.9,775.17 ; v1(1987.39,317.39) J7.2@1987.39,377.87
  Layer 2 w6: v1(1165,712) 1361.72,712 1485.9,587.82 1485.9,521.82 1485.9,484.82 1518.82,451.9 1555.82,451.9 1930.1,451.9 1987.39,394.61 v1(1987.39,317.39)
FDCAN_H: FL1.4 R17.1 TP1.1 XT1.4 XT2.4 | length 3382.2
  Top Layer w6: FL1.4@1777.41,992.28 1782.03,987.66 1782.03,972.54 1789.57,965 1834.98,965 1848,978.02 1848,1024 R17.1@1823,1049 v1(1823,1142.9)
  Bottom Layer w6: XT2.4@547.83,1361.43 547.83,1351.17 582,1317 658,1317 722,1381 889,1381 ; TP1.1@885.87,1364.13 TP1.1@890,1360 ; TP1.1@890,1350 TP1.1@890,1360 ; XT1.4@2650,1721.27 2622.56,1693.82 2622.56,1670.56 2691.1,1602.01 2691.1,1284.99 2566,1159.89 2566,1044.89 2503.01,981.9 2213.99,981.9 2176,1019.89 2176,1097 2130.1,1142.9 v1(1823,1142.9) 1777.1,1142.9 1762,1158 1217,1158 1015,1360 942,1360 921,1381 889,1381 ; 889,1381 890,1380 TP1.1@890,1360
FDCAN_L: FL1.3 R18.2 TP3.1 XT1.3 XT2.3 | length 3173.6
  Top Layer w6: v1(1785,1169) R18.2@1785,1049 1823.72,1010.28 1823.72,997.15 FL1.3@1828.59,992.28
  Bottom Layer w6: XT2.3@626.57,1361.43 658.15,1393 890,1393 ; TP3.1@890,1430 890,1393 ; XT1.3@2571.26,1721.27 2571.26,1704.74 2679,1597 2679,1290 2552.9,1163.9 2552.9,1048.9 2498,994 2219,994 2188.1,1024.9 2188.1,1102.01 2135.11,1155 1847,1155 1833,1169 v1(1785,1169) 1221,1169 1016.5,1373.5 946.5,1373.5 927,1393 890,1393
FDCAN_RX1: IC2.4 IC3.46 R16.2 SB6.2 | length 1570.5
  Top Layer w6: IC3.46@1038.05,1046.88 IC3.46@1038.1,1046.83 1038.55,1047.28 1038.55,1124.55 R16.2@1039,1125 1039.5,1125.5 1067.5,1125.5 v1(1068,1126) ; v1(1435,544) 1435,741 v1(1468,774)
  Top Layer w8: v1(1578,785) 1578,813.7 IC2.4@1578.91,814.61
  Layer 2 w6: v1(1435,544) 1435,486 1595,326 v2(1595,267)
  Bottom Layer w6: v1(1068,1126) 1229,965 1417,965 1450,932 1565,932 1578,919 v1(1578,785) 1574.75,785 1563.75,774 v1(1468,774)
  Bottom Layer w8: SB6.2@1594,267.5 1594.5,267 v2(1595,267)
FDCAN_TX1: IC2.1 IC3.47 | length 691.3
  Top Layer w6: IC3.47@1018.42,1046.83 1018.71,1047.12 1018.71,1093.71 v1(1019,1094)
  Top Layer w8: v1(1536,905) 1538,905 1551.61,891.39 IC2.1@1578.91,891.39
  Bottom Layer w6: v1(1019,1094) 1071,1094 1217,948 1405,948 1448,905 v1(1536,905)
FLASH_CLK: IC3.13 IC5.6 | length 641.8
  Top Layer w8: IC5.6@962.27,592 961.27,591 854,591 844,601 844,620 844,624 839.31,628.69 803.71,628.69 800.05,632.35 800.05,637.23 803.71,640.89 853.04,640.89 856.7,644.55 856.7,649.43 853.04,653.09 803.71,653.09 800.05,656.75 800.05,661.63 803.71,665.29 853.04,665.29 856.7,668.95 856.7,673.83 853.04,677.49 848.69,677.49 844,682.17 844,690.8 844,691 859,706 990,706 998.73,714.73 IC3.13@998.73,775.17
FLASH_CS: IC3.16 IC5.1 | length 640.6
  Top Layer w8: IC3.16@1057.79,775.17 1057.79,596.21 1078.5,575.5 1087.54,566.46 1094.16,566.46 1126.59,598.89 1131.77,598.89 1135.22,595.44 1135.22,590.26 1095.64,550.68 1095.64,545.5 1099.09,542.05 1104.26,542.05 1143.84,581.64 1149.02,581.64 1152.47,578.18 1152.47,573.01 1112.89,533.43 1112.89,528.25 1116.34,524.8 1121.52,524.8 1122.04,525.33 1128.67,525.33 1131.5,522.5 1162,492 IC5.1@1245.73,492
FLASH_MISO: IC3.14 IC5.2 | length 636.7
  Top Layer w8: IC3.14@1018.42,775.17 1018.42,581.58 1143,457 1280,457 1295,472 1295,524 1284.49,534.51 1253.22,534.51 IC5.2@1245.73,542
FLASH_MOSI: IC3.15 IC5.5 | length 516.4
  Top Layer w8: v1(892,643) 961.27,643 IC5.5@962.27,642 ; IC3.15@1038.1,775.17 1038.55,774.72 1038.55,724.45 v1(1039,724)
  Bottom Layer w8: v1(892,643) 932,643 936,643 940.69,647.69 940.69,668.87 944.35,672.53 949.23,672.53 952.89,668.87 952.89,627.09 956.55,623.43 961.43,623.43 965.09,627.09 965.09,668.87 968.75,672.53 973.63,672.53 977.29,668.87 977.29,627.09 980.95,623.43 985.83,623.43 989.49,627.09 989.49,638.31 994.17,643 1005.06,643 1026,643 1039,656 v1(1039,724)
